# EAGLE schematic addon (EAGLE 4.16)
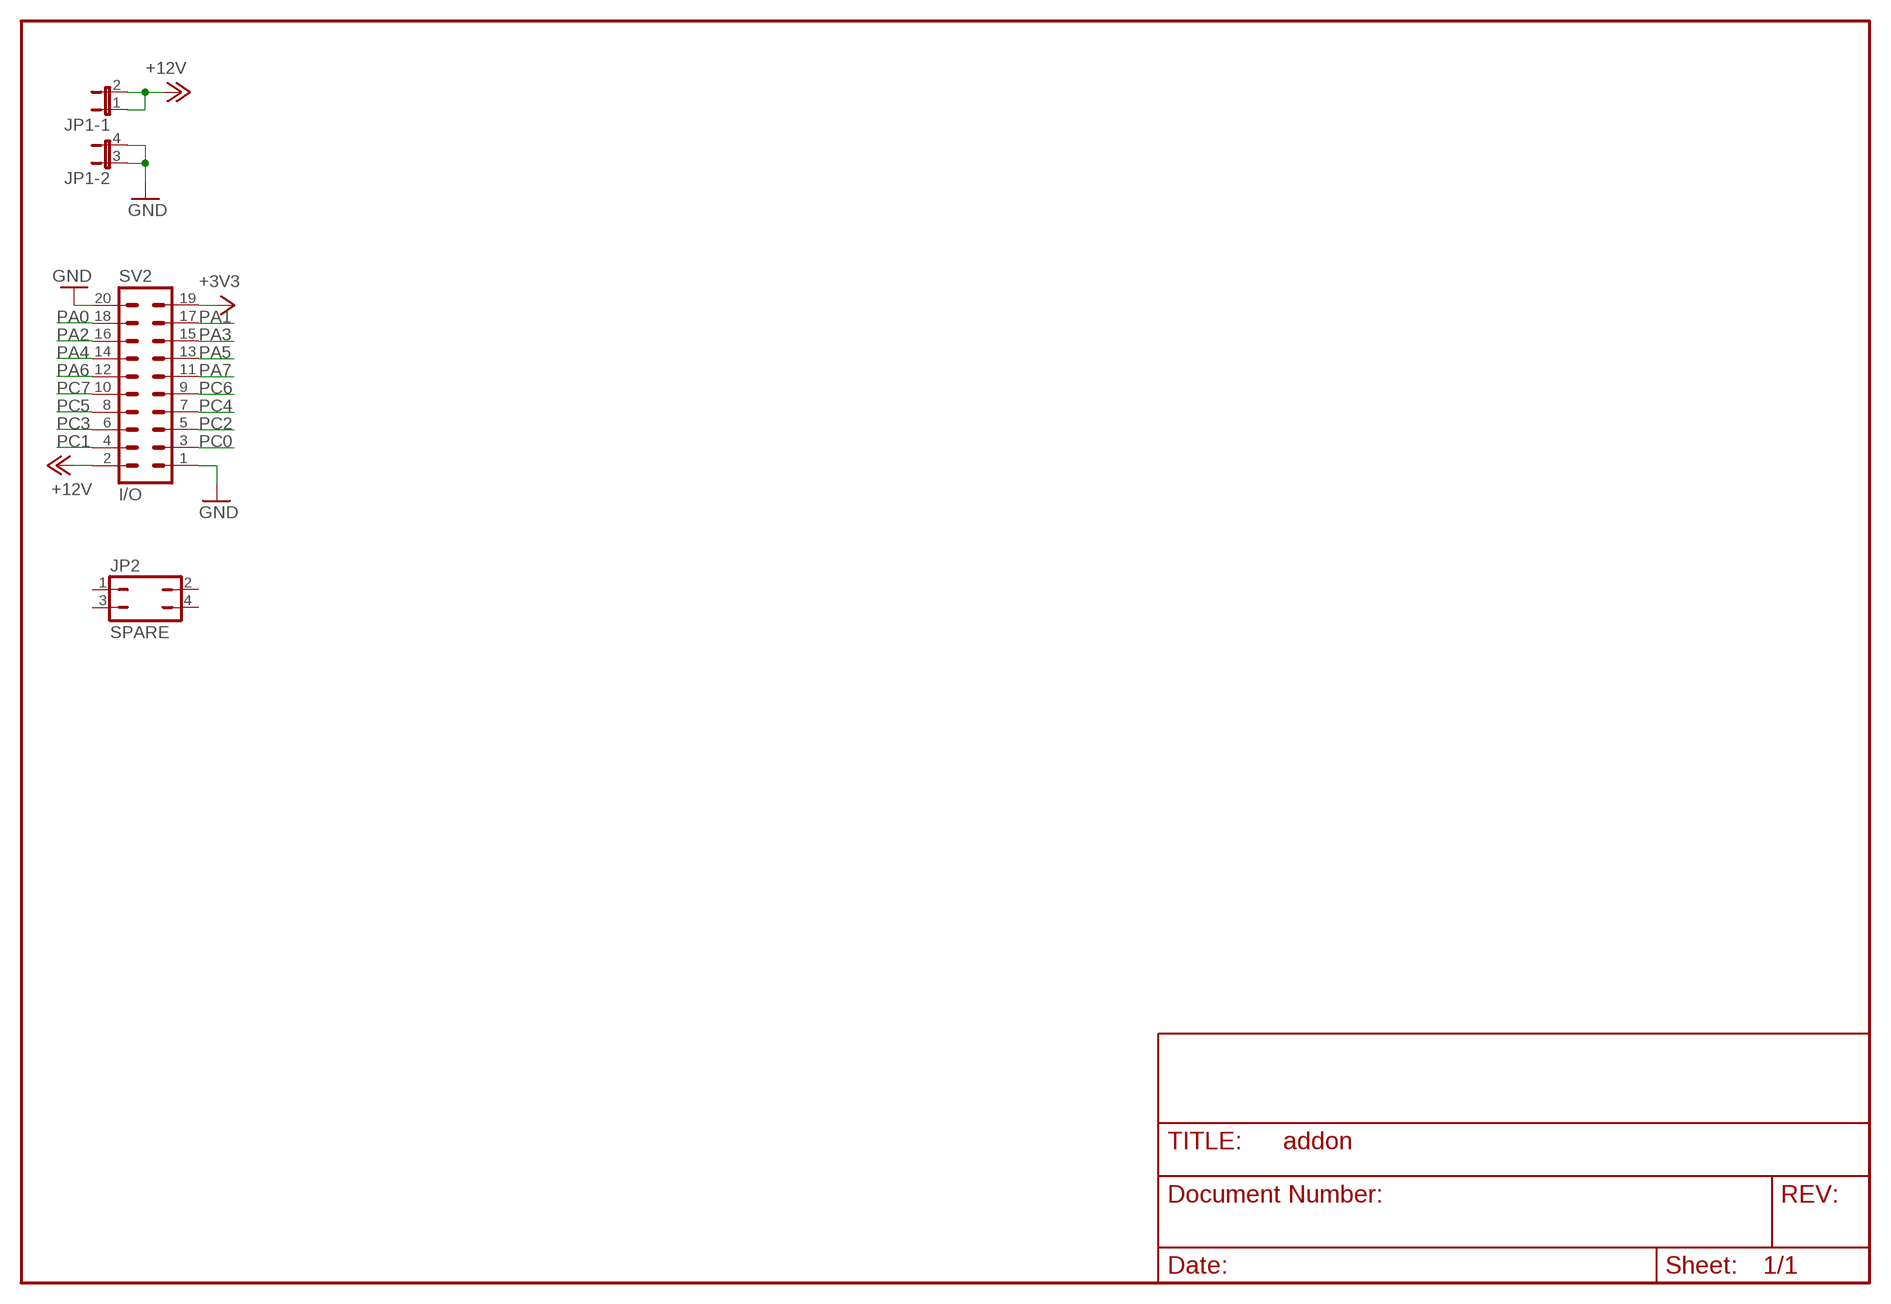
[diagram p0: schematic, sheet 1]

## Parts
JP1  JP2QE  [JP2Q]
JP2  SPARE  JP2Q  [JP2Q]
SV2  I/O  MA10-2  [MA10-2]

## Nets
+3V3: SV2.19
+12V: JP1.1 JP1.2 SV2.2
GND: JP1.3 JP1.4 SV2.1 SV2.20
PA0: SV2.18
PA1: SV2.17
PA2: SV2.16
PA3: SV2.15
PA4: SV2.14
PA5: SV2.13
PA6: SV2.12
PA7: SV2.11
PC0: SV2.3
PC1: SV2.4
PC2: SV2.5
PC3: SV2.6
PC4: SV2.7
PC5: SV2.8
PC6: SV2.9
PC7: SV2.10
Unconnected: JP2.1 JP2.2 JP2.3 JP2.4

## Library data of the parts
JP1 = jumper:JP2QE: JUMPER
JP2 = jumper:JP2Q: JUMPER
SV2 = con-lstb:MA10-2: PIN HEADER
